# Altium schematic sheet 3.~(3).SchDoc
size 420 x 297 mm
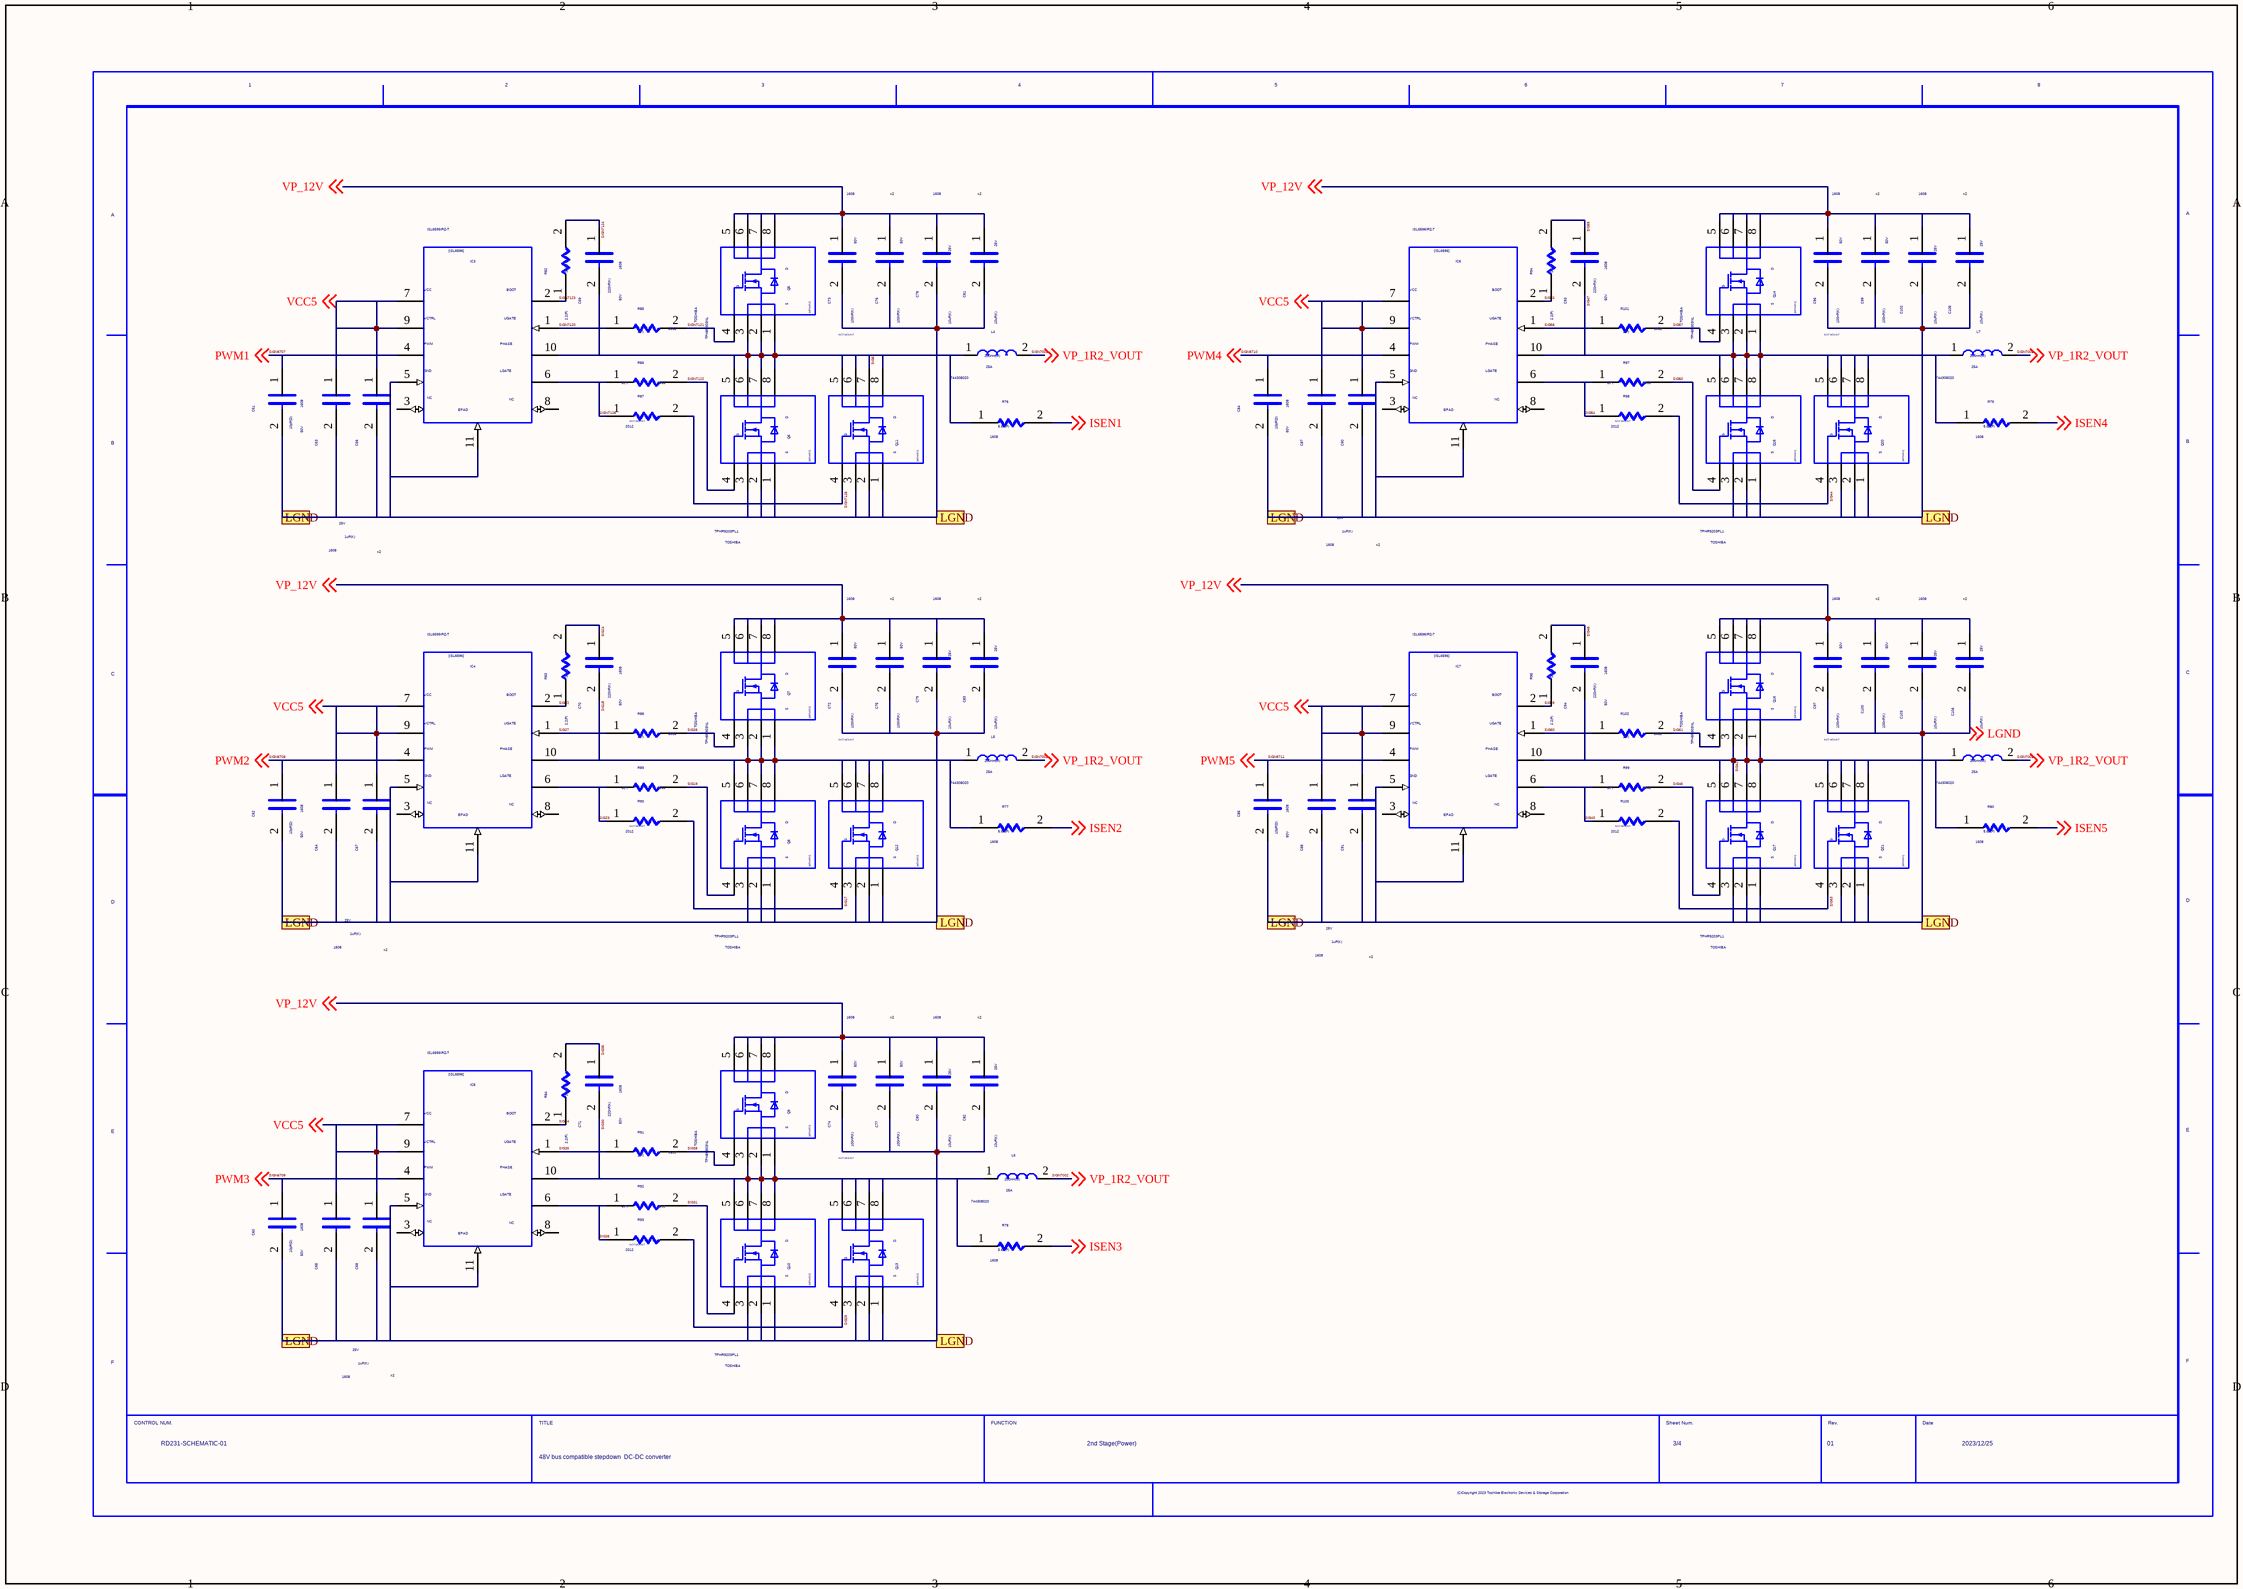
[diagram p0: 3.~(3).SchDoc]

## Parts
C60  VAL1: 10pF(D)  VAL2: 50V  SIZECODESMD: 1608  (hidden comment: C)
C61  VAL1: 10pF(D)  VAL2: 50V  SIZECODESMD: 1608  (hidden comment: C)
C62  VAL1: 10pF(D)  VAL2: 50V  SIZECODESMD: 1608  (hidden comment: C)
C63  C  (value not drawn)
C64  C  (value not drawn)
C65  C  (value not drawn)
C66  VAL1: 1uF(K)  VAL2: 25V  SIZECODESMD: 1608  (hidden comment: C)
C67  VAL1: 1uF(K)  VAL2: 25V  SIZECODESMD: 1608  (hidden comment: C)
C68  VAL1: 1uF(K)  VAL2: 25V  SIZECODESMD: 1608  (hidden comment: C)
C69  VAL1: 220nF(K)  VAL2: 50V  SIZECODESMD: 1608  (hidden comment: C)
C70  VAL1: 220nF(K)  VAL2: 50V  SIZECODESMD: 1608  (hidden comment: C)
C71  VAL1: 220nF(K)  VAL2: 50V  SIZECODESMD: 1608  (hidden comment: C)
C72  VAL1: 100nF(K)  VAL2: 50V  SIZECODESMD: 1608  (hidden comment: C)
C73  VAL1: 100nF(K)  VAL2: 50V  SIZECODESMD: 1608  (hidden comment: C)
C74  VAL1: 100nF(K)  VAL2: 50V  SIZECODESMD: 1608  (hidden comment: C)
C75  VAL1: 100nF(K)  VAL2: 50V  (hidden comment: C)
C76  VAL1: 100nF(K)  VAL2: 50V  (hidden comment: C)
C77  VAL1: 100nF(K)  VAL2: 50V  (hidden comment: C)
C78  VAL1: 10uF(K)  VAL2: 25V  SIZECODESMD: 1608  (hidden comment: C)
C79  VAL1: 10uF(K)  VAL2: 25V  SIZECODESMD: 1608  (hidden comment: C)
C80  VAL1: 10uF(K)  VAL2: 25V  SIZECODESMD: 1608  (hidden comment: C)
C81  VAL1: 10uF(K)  VAL2: 25V  (hidden comment: C)
C82  VAL1: 10uF(K)  VAL2: 25V  (hidden comment: C)
C83  VAL1: 10uF(K)  VAL2: 25V  (hidden comment: C)
C84  VAL1: 10pF(D)  VAL2: 50V  SIZECODESMD: 1608  (hidden comment: C)
C85  VAL1: 10pF(D)  VAL2: 50V  SIZECODESMD: 1608  (hidden comment: C)
C87  C  (value not drawn)
C88  C  (value not drawn)
C90  VAL1: 1uF(K)  VAL2: 25V  SIZECODESMD: 1608  (hidden comment: C)
C91  VAL1: 1uF(K)  VAL2: 25V  SIZECODESMD: 1608  (hidden comment: C)
C93  VAL1: 220nF(K)  VAL2: 50V  SIZECODESMD: 1608  (hidden comment: C)
C94  VAL1: 220nF(K)  VAL2: 50V  SIZECODESMD: 1608  (hidden comment: C)
C96  VAL1: 100nF(K)  VAL2: 50V  SIZECODESMD: 1608  (hidden comment: C)
C97  VAL1: 100nF(K)  VAL2: 50V  SIZECODESMD: 1608  (hidden comment: C)
C99  VAL1: 100nF(K)  VAL2: 50V  (hidden comment: C)
C100  VAL1: 100nF(K)  VAL2: 50V  (hidden comment: C)
C102  VAL1: 10uF(K)  VAL2: 25V  SIZECODESMD: 1608  (hidden comment: C)
C103  VAL1: 10uF(K)  VAL2: 25V  SIZECODESMD: 1608  (hidden comment: C)
C105  VAL1: 10uF(K)  VAL2: 25V  (hidden comment: C)
C106  VAL1: 10uF(K)  VAL2: 25V  (hidden comment: C)
IC3  VAL3: ISL6596IRZ-T  (hidden comment: ISL6596)
IC4  VAL3: ISL6596IRZ-T  (hidden comment: ISL6596)
IC5  VAL3: ISL6596IRZ-T  (hidden comment: ISL6596)
IC6  VAL3: ISL6596IRZ-T  (hidden comment: ISL6596)
IC7  VAL3: ISL6596IRZ-T  (hidden comment: ISL6596)
L4  VAL1: 200nH(M)  VAL2: 25A  VAL3: 744308020  (hidden comment: L)
L5  VAL1: 200nH(M)  VAL2: 25A  VAL3: 744308020  (hidden comment: L)
L6  VAL1: 200nH(M)  VAL2: 25A  VAL3: 744308020  (hidden comment: L)
L7  VAL1: 200nH(M)  VAL2: 25A  VAL3: 744308020  (hidden comment: L)
L8  VAL1: 200nH(M)  VAL2: 25A  VAL3: 744308020  (hidden comment: L)
Q5  VAL3: TPH8R903NL  USERCOMPTEXT3: TOSHIBA  (hidden comment: MFNKR2)
Q6  VAL3: TPHR9203PL1  USERCOMPTEXT3: TOSHIBA  (hidden comment: MFNKR2)
Q7  VAL3: TPH8R903NL  USERCOMPTEXT3: TOSHIBA  (hidden comment: MFNKR2)
Q8  VAL3: TPHR9203PL1  USERCOMPTEXT3: TOSHIBA  (hidden comment: MFNKR2)
Q9  VAL3: TPH8R903NL  USERCOMPTEXT3: TOSHIBA  (hidden comment: MFNKR2)
Q10  VAL3: TPHR9203PL1  USERCOMPTEXT3: TOSHIBA  (hidden comment: MFNKR2)
Q11  NOTMOUNT: NOT MOUNT  (hidden comment: MFNKR2)
Q12  NOTMOUNT: NOT MOUNT  (hidden comment: MFNKR2)
Q13  NOTMOUNT: NOT MOUNT  (hidden comment: MFNKR2)
Q14  VAL3: TPH8R903NL  USERCOMPTEXT3: TOSHIBA  (hidden comment: MFNKR2)
Q15  VAL3: TPHR9203PL1  USERCOMPTEXT3: TOSHIBA  (hidden comment: MFNKR2)
Q16  VAL3: TPH8R903NL  USERCOMPTEXT3: TOSHIBA  (hidden comment: MFNKR2)
Q17  VAL3: TPHR9203PL1  USERCOMPTEXT3: TOSHIBA  (hidden comment: MFNKR2)
Q20  NOTMOUNT: NOT MOUNT  (hidden comment: MFNKR2)
Q21  NOTMOUNT: NOT MOUNT  (hidden comment: MFNKR2)
R76  VAL1: 5.6k(F)  SIZECODESMD: 1608  (hidden comment: R)
R77  VAL1: 5.6k(F)  SIZECODESMD: 1608  (hidden comment: R)
R78  VAL1: 5.6k(F)  SIZECODESMD: 1608  (hidden comment: R)
R79  VAL1: 5.6k(F)  SIZECODESMD: 1608  (hidden comment: R)
R80  VAL1: 5.6k(F)  SIZECODESMD: 1608  (hidden comment: R)
R82  VAL1: 2.2(F)  SIZECODESMD: 2012  (hidden comment: R)
R83  VAL1: 2.2(F)  SIZECODESMD: 2012  (hidden comment: R)
R84  VAL1: 2.2(F)  SIZECODESMD: 2012  (hidden comment: R)
R85  VAL1: 1(F)  SIZECODESMD: 2012  (hidden comment: R)
R86  VAL1: 1(F)  SIZECODESMD: 2012  (hidden comment: R)
R87  NOTMOUNT: NOT MOUNT  SIZECODESMD: 2012  (hidden comment: R)
R88  VAL1: 1(F)  SIZECODESMD: 2012  (hidden comment: R)
R89  VAL1: 1(F)  SIZECODESMD: 2012  (hidden comment: R)
R90  NOTMOUNT: NOT MOUNT  SIZECODESMD: 2012  (hidden comment: R)
R91  VAL1: 1(F)  SIZECODESMD: 2012  (hidden comment: R)
R92  VAL1: 1(F)  SIZECODESMD: 2012  (hidden comment: R)
R93  NOTMOUNT: NOT MOUNT  SIZECODESMD: 2012  (hidden comment: R)
R94  VAL1: 2.2(F)  SIZECODESMD: 2012  (hidden comment: R)
R95  VAL1: 2.2(F)  SIZECODESMD: 2012  (hidden comment: R)
R97  VAL1: 1(F)  SIZECODESMD: 2012  (hidden comment: R)
R98  NOTMOUNT: NOT MOUNT  SIZECODESMD: 2012  (hidden comment: R)
R99  VAL1: 1(F)  SIZECODESMD: 2012  (hidden comment: R)
R100  NOTMOUNT: NOT MOUNT  SIZECODESMD: 2012  (hidden comment: R)
R101  VAL1: 1(F)  SIZECODESMD: 2012  (hidden comment: R)
R102  VAL1: 1(F)  SIZECODESMD: 2012  (hidden comment: R)
U?  DATE: 2023/12/25  FUNCTION: 2nd Stage(Power)  DRAWINGNUMBER: RD231-SCHEMATIC-01  SHEETNUMBER: 3/4  REVISION: 01  TITLE: 48V bus compatible stepdown / DC-DC converter  (hidden comment: WAKU_DEF100)

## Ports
LGND

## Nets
ISEN1: R76.2 ; off-sheet ISEN1
ISEN2: R77.2 ; off-sheet ISEN2
ISEN3: R78.2 ; off-sheet ISEN3
ISEN4: R79.2 ; off-sheet ISEN4
ISEN5: R80.2 ; off-sheet ISEN5
LGND: C60.2 C61.2 C62.2 C63.2 C64.2 C65.2 C66.2 C67.2 C68.2 C72.2 C73.2 C74.2 C75.2 C76.2 C77.2 C78.2 C79.2 C80.2 C81.2 C82.2 C83.2 C84.2 C85.2 C87.2 C88.2 C90.2 C91.2 C96.2 C97.2 C99.2 C100.2 C102.2 C103.2 C105.2 C106.2 IC3.5 IC3.11 IC4.5 IC4.11 IC5.5 IC5.11 IC6.5 IC6.11 IC7.5 IC7.11 Q6.1 Q6.2 Q6.3 Q8.1 Q8.2 Q8.3 Q10.1 Q10.2 Q10.3 Q11.1 Q11.2 Q11.3 Q12.1 Q12.2 Q12.3 Q13.1 Q13.2 Q13.3 Q15.1 Q15.2 Q15.3 Q17.1 Q17.2 Q17.3 Q20.1 Q20.2 Q20.3 Q21.1 Q21.2 Q21.3 ; off-sheet LGND, port LGND
SIG5: C69.2 IC3.10 L4.1 Q5.1 Q5.2 Q5.3 Q6.5 Q6.6 Q6.7 Q6.8 Q11.5 Q11.6 Q11.7 Q11.8 R76.1
SIG17: Q12.4 R90.2
SIG18: C70.2 IC4.10 L5.1 Q7.1 Q7.2 Q7.3 Q8.5 Q8.6 Q8.7 Q8.8 Q12.5 Q12.6 Q12.7 Q12.8 R77.1
SIG19: Q8.4 R89.2
SIG22: IC4.2 R83.1
SIG23: IC4.6 R89.1 R90.1
SIG24: C70.1 R83.2
SIG26: Q7.4 R88.2
SIG27: IC4.1 R88.1
SIG29: Q13.4 R93.2
SIG30: C71.2 IC5.10 L6.1 Q9.1 Q9.2 Q9.3 Q10.5 Q10.6 Q10.7 Q10.8 Q13.5 Q13.6 Q13.7 Q13.8 R78.1
SIG31: Q10.4 R92.2
SIG34: IC5.2 R84.1
SIG35: IC5.6 R92.1 R93.1
SIG36: C71.1 R84.2
SIG38: Q9.4 R91.2
SIG39: IC5.1 R91.1
SIG41: C94.2 IC7.10 L8.1 Q16.1 Q16.2 Q16.3 Q17.5 Q17.6 Q17.7 Q17.8 Q21.5 Q21.6 Q21.7 Q21.8 R80.1
SIG43: IC7.6 R99.1 R100.1
SIG44: Q20.4 R98.2
SIG46: Q17.4 R99.2
SIG47: C93.2 IC6.10 L7.1 Q14.1 Q14.2 Q14.3 Q15.5 Q15.6 Q15.7 Q15.8 Q20.5 Q20.6 Q20.7 Q20.8 R79.1
SIG48: C94.1 R95.2
SIG49: IC7.2 R95.1
SIG50: Q15.4 R97.2
SIG53: IC6.2 R94.1
SIG54: IC6.6 R97.1 R98.1
SIG55: C93.1 R94.2
SIG57: Q14.4 R101.2
SIG58: IC6.1 R101.1
SIG60: IC7.1 R102.1
SIG61: Q16.4 R102.2
SIG63: Q21.4 R100.2
SIGN6707: C61.1 IC3.4 ; off-sheet PWM1  [also labelled PWM1]
SIGN6708: C62.1 IC4.4 ; off-sheet PWM2  [also labelled PWM2]
SIGN6709: C60.1 IC5.4 ; off-sheet PWM3  [also labelled PWM3]
SIGN6710: C84.1 IC6.4 ; off-sheet PWM4  [also labelled PWM4]
SIGN6711: C85.1 IC7.4 ; off-sheet PWM5  [also labelled PWM5]
SIGN7002: L4.2 L5.2 L6.2 L7.2 L8.2 ; off-sheet VP_1R2_VOUT  [also labelled VP_1R2_VOUT]
SIGN7120: IC3.1 R85.1
SIGN7121: Q5.4 R85.2
SIGN7122: Q6.4 R86.2
SIGN7123: IC3.2 R82.1
SIGN7124: C69.1 R82.2
SIGN7125: Q11.4 R87.2
SIGN7126: IC3.6 R86.1 R87.1
VCC5: C63.1 C64.1 C65.1 C66.1 C67.1 C68.1 C87.1 C88.1 C90.1 C91.1 IC3.7 IC3.9 IC4.7 IC4.9 IC5.7 IC5.9 IC6.7 IC6.9 IC7.7 IC7.9 ; off-sheet VCC5
VP_12V: C72.1 C73.1 C74.1 C75.1 C76.1 C77.1 C78.1 C79.1 C80.1 C81.1 C82.1 C83.1 C96.1 C97.1 C99.1 C100.1 C102.1 C103.1 C105.1 C106.1 Q5.5 Q5.6 Q5.7 Q5.8 Q7.5 Q7.6 Q7.7 Q7.8 Q9.5 Q9.6 Q9.7 Q9.8 Q14.5 Q14.6 Q14.7 Q14.8 Q16.5 Q16.6 Q16.7 Q16.8 ; off-sheet VP_12V

Not connected (* = marked no-connect by the designer): IC3 3 8; IC4 3 8; IC5 3 8; IC6 3 8; IC7 3 8

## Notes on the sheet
- x2

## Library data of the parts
C60-C62 C84 C85 = C: FNPARTSNAMEG: CHIP CERAMIC CAPACITOR (1608); OriginalSymbolOrigin: (2540,7620); FNCLASSCODEG: P03-03; PCODE: P03039185229; USEWITHSCHEMA: YES; MFMOUNTSYMBOLP: 80; FUNCN: G36030011013; MFFORMINGDIVP: KC; MFPACKAGEMETHOP: S; MFSOLDERINGPROP: .; COMPONENTNAME: G36030011013_package; GCOUNT: 1; TOLERANCE: D
C63-C65 C87 C88 = C: FNPARTSNAMEG: CHIP CERAMIC CAPACITOR (1608); OriginalSymbolOrigin: (2540,7620); FNCLASSCODEG: P03-03; PCODE: P03039992230; USEWITHSCHEMA: YES; VAL1: 1uF(K); VAL2: 25V; MFMOUNTSYMBOLP: 80; FUNCN: G36030011433; SIZECODESMD: 1608; MFFORMINGDIVP: KC; MFPACKAGEMETHOP: S; MFSOLDERINGPROP: .; COMPONENTNAME: G36030011433_package; GCOUNT: 1
C66-C68 C78-C80 C90 C91 C102 C103 = C: FNPARTSNAMEG: CHIP CERAMIC CAPACITOR (1608); OriginalSymbolOrigin: (2540,7620); FNCLASSCODEG: P03-03; PCODE: P03039992230; USEWITHSCHEMA: YES; MFMOUNTSYMBOLP: 80; FUNCN: G36030011433; MFFORMINGDIVP: KC; MFPACKAGEMETHOP: S; MFSOLDERINGPROP: .; COMPONENTNAME: G36030011433_package; GCOUNT: 1
C69-C71 C93 C94 = C: FNPARTSNAMEG: CHIP CERAMIC CAPACITOR (1608); OriginalSymbolOrigin: (2540,7620); FNCLASSCODEG: P03-03; PCODE: P03039ABE123; USEWITHSCHEMA: YES; MFMOUNTSYMBOLP: 80; FUNCN: G36030104104; MFFORMINGDIVP: KC; MFPACKAGEMETHOP: S; MFSOLDERINGPROP: .; COMPONENTNAME: G36030104104_package; GCOUNT: 1
C72-C74 C96 C97 = C: FNPARTSNAMEG: CHIP CERAMIC CAPACITOR (1608); OriginalSymbolOrigin: (2540,7620); FNCLASSCODEG: P03-03; PCODE: P03039996139; USEWITHSCHEMA: YES; MFMOUNTSYMBOLP: 80; FUNCN: G36030011419; MFFORMINGDIVP: KC; MFPACKAGEMETHOP: S; MFSOLDERINGPROP: .; COMPONENTNAME: G36030011419_package; GCOUNT: 1
C75-C77 C99 C100 = C: FNPARTSNAMEG: CHIP CERAMIC CAPACITOR (1608); OriginalSymbolOrigin: (2540,7620); FNCLASSCODEG: P03-03; PCODE: P03039996139; USEWITHSCHEMA: YES; MFMOUNTSYMBOLP: 80; FUNCN: G36030011419; SIZECODESMD: 1608; MFFORMINGDIVP: KC; MFPACKAGEMETHOP: S; MFSOLDERINGPROP: .; COMPONENTNAME: G36030011419_package; GCOUNT: 1
C81-C83 C105 C106 = C: FNPARTSNAMEG: CHIP CERAMIC CAPACITOR (1608); OriginalSymbolOrigin: (2540,7620); FNCLASSCODEG: P03-03; PCODE: P03039992230; USEWITHSCHEMA: YES; MFMOUNTSYMBOLP: 80; FUNCN: G36030011433; SIZECODESMD: 1608; MFFORMINGDIVP: KC; MFPACKAGEMETHOP: S; MFSOLDERINGPROP: .; COMPONENTNAME: G36030011433_package; GCOUNT: 1
IC3-IC7 = ISL6596: PARTS: 1; SAVECOUNT: 32; SAVEAREA0: -56845,-25936,87219,39707; TIME: 14:04:55; UPDATEUSER: sptcae13; UPDATETIME: 17:09:04; DEVICENAME: 74HC244AF; DEVICE: 74VHC245; PKG_TYPE: 20PIN; LEVEL: STD; HETERO: 74VHC245,74VHC245_P; OriginalSymbolOrigin: (5080,27940); COMP: G36470287016
L4-L8 = L: OriginalSymbolOrigin: (2540,5080); USEWITHSCHEMA: YES; OUMEMAKERKATAMEI: 7443082022; OUMEMAKER: Wurth; COMPONENTNAME: pinass:L_func:L; GCOUNT: 1
Q5-Q10 Q14-Q17 = MFNKR2: SAVEAREA0: -9199,-39,32138,22820; TIME: 18:57:44; UPDATEUSER: q91866sr; UPDATETIME: 12:36:02; SAVECOUNT: 10; OriginalSymbolOrigin: (5080,20320); USEWITHSCHEMA: YES; OUMEMAKERKATAMEI: TPH6R003NL; COMPONENTNAME: MFNKR2_MFNKR2; GCOUNT: 1
Q11-Q13 Q20 Q21 = MFNKR2: SAVEAREA0: -9199,-39,32138,22820; TIME: 18:57:44; UPDATEUSER: q91866sr; UPDATETIME: 12:36:02; SAVECOUNT: 10; OriginalSymbolOrigin: (5080,20320); USEWITHSCHEMA: YES; OUMEMAKERKATAMEI: TPH6R003NL; OUMEMAKER: TOSHIBA; COMPONENTNAME: MFNKR2_MFNKR2; GCOUNT: 1
R76-R80 = R: OriginalSymbolOrigin: (5080,5080); VAL2: 62.5mW
R82-R84 R94 R95 = R: FNPARTSNAMEG: CHIP RESISTOR (2012); OriginalSymbolOrigin: (5080,5080); FNCLASSCODEG: P01-08; PCODE: P01048019214; USEWITHSCHEMA: YES; VAL2: 125mW; NUMBEROFELEMENT: 0; MFMOUNTSYMBOLP: 90; FUNCN: G36010106012; MFFORMINGDIVP: KC; MFPACKAGEMETHOP: S; MFSOLDERINGPROP: .; COMPONENTNAME: G36010106012_package; GCOUNT: 1
R85 R86 R88 R89 R91 R92 R97 R99 R101 R102 = R: FNPARTSNAMEG: CHIP RESISTOR (2012); OriginalSymbolOrigin: (5080,5080); FNCLASSCODEG: P01-08; PCODE: P01048017210; USEWITHSCHEMA: YES; VAL2: 125mW; NUMBEROFELEMENT: 0; MFMOUNTSYMBOLP: 90; FUNCN: G36010106081; MFFORMINGDIVP: KC; MFPACKAGEMETHOP: S; MFSOLDERINGPROP: .; COMPONENTNAME: G36010106081_package; GCOUNT: 1
R87 R90 R93 R98 R100 = R: FNPARTSNAMEG: CHIP RESISTOR (2012); OriginalSymbolOrigin: (5080,5080); FNCLASSCODEG: P01-08; PCODE: P01048017210; USEWITHSCHEMA: YES; NUMBEROFELEMENT: 0; MFMOUNTSYMBOLP: 90; FUNCN: G36010106081; MFFORMINGDIVP: KC; MFPACKAGEMETHOP: S; MFSOLDERINGPROP: .; COMPONENTNAME: G36010106081_package; GCOUNT: 1
U? = WAKU_DEF100: PLOTTIME: HH:MM; SAVEAREA0: 315434,-7824,400773,39368; TIME: 14:26:19; UPDATEUSER: sptcae13; UPDATETIME: 11:36:35; SAVECOUNT: 8; OriginalSymbolOrigin: (10160,284480)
